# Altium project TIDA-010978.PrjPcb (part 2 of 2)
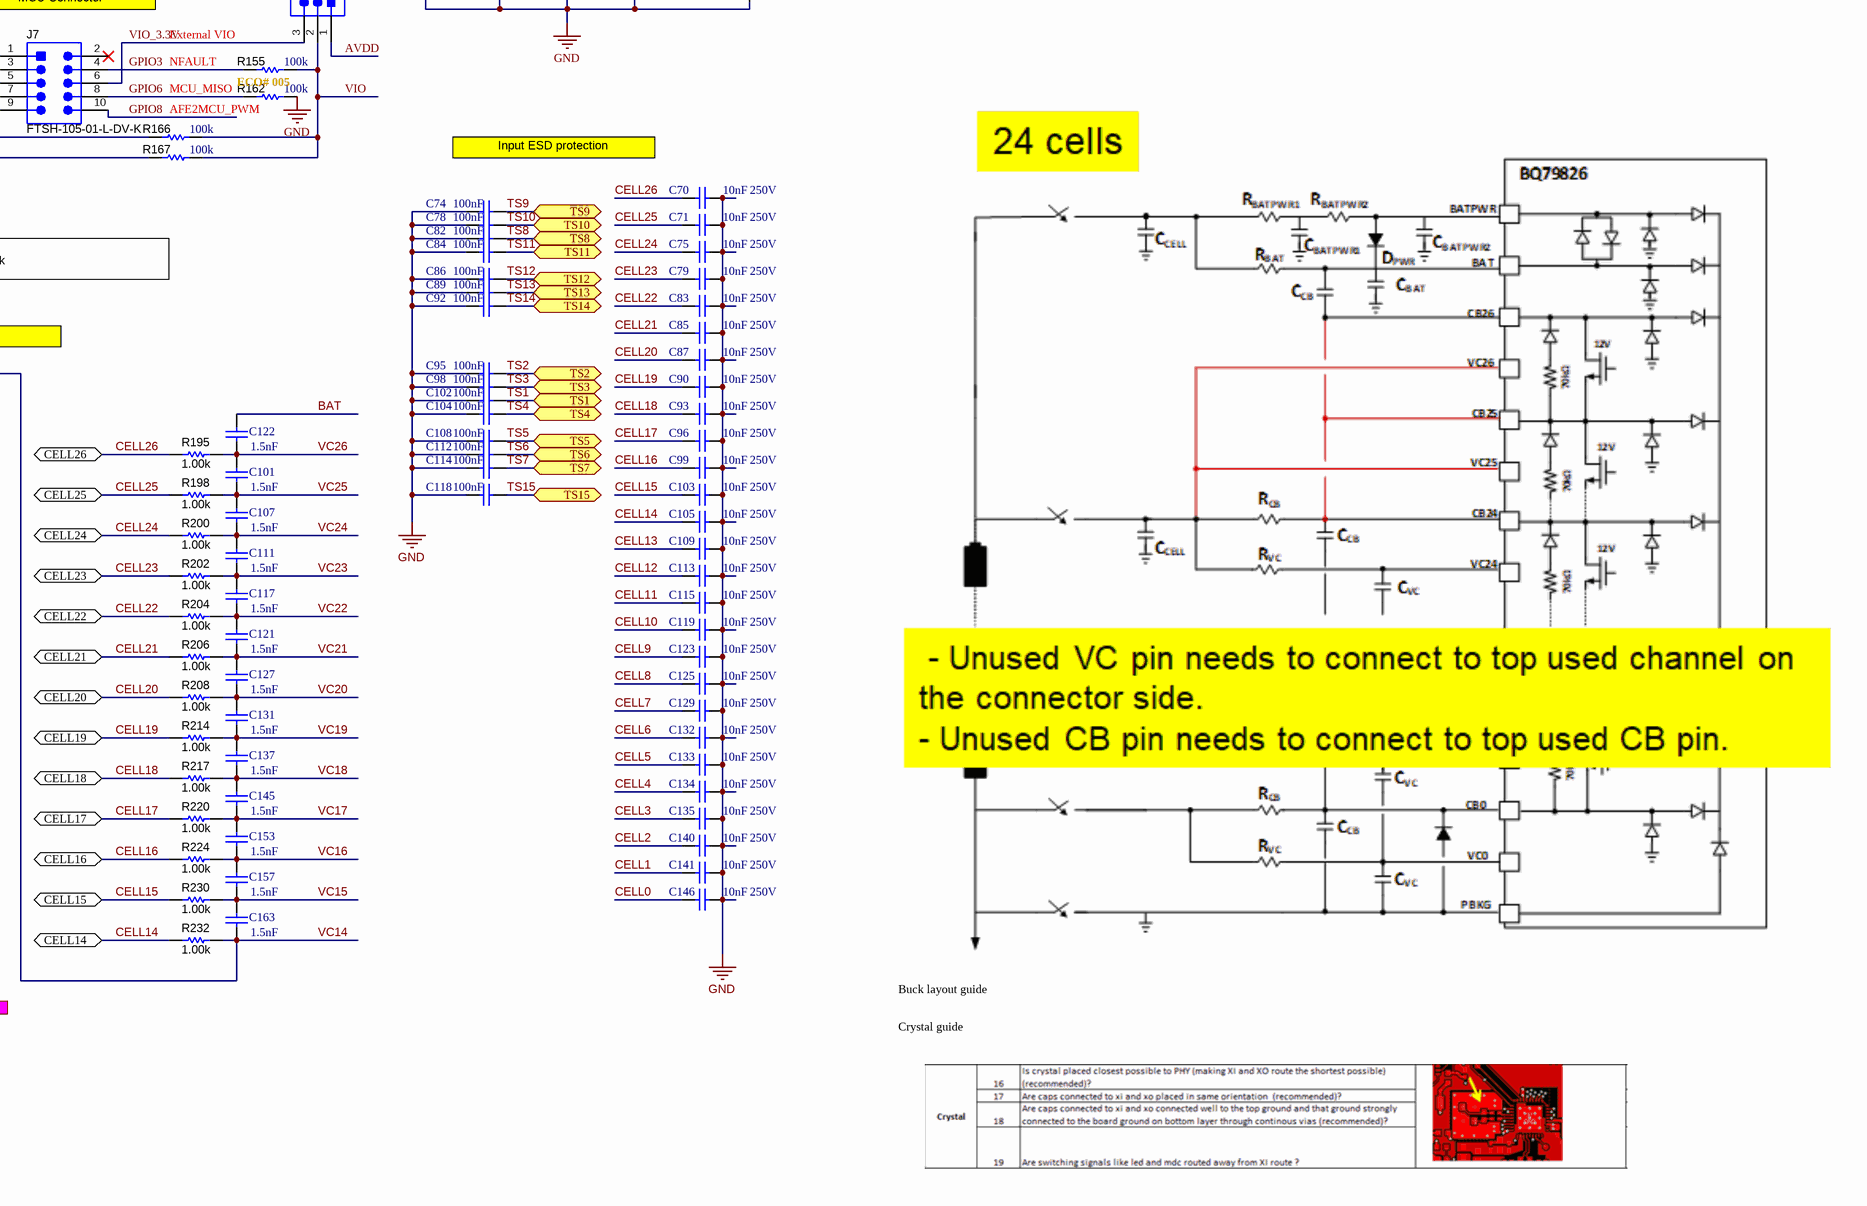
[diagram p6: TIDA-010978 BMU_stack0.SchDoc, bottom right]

## Sheet TIDA-010978 BMU_stack0.SchDoc (continued)

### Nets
GND: AVDD_LED1.1(K) C9.1 C10.2 C11.1 C16.1 C17.1 C18.2 C19.1 C20.1 C21.1 C22.1 C23.1 C24.1 C29.1 C30.1 C32.2 C33.2 C40.1 C51.2 C52.1 C58.1 C59.2 C60.2 C61.2 C62.2 C63.2 C64.2 C65.2 C66.2 C67.2 C68.2 C69.2 C70.1 C71.1 C72.2 C73.2 C74.1 C75.1 C76.2 C77.2 C78.1 C79.1 C80.2 C81.2 C82.1 C83.1 C84.1 C85.1 C86.1 C87.1 C88.2 C89.1 C90.1 C92.1 C93.1 C94.2 C95.1 C96.1 C98.1 C99.1 C102.1 C103.1 C104.1 C105.1 C108.1 C109.1 C112.1 C113.1 C114.1 C115.1 C118.1 C119.1 C123.1 C124.2 C125.1 C128.2 C129.1 C132.1 C133.1 C134.1 C135.1 C138.2 C139.2 C140.1 C141.1 C142.2 C143.1 C146.1 C147.2 C148.2 C149.1 C150.1 C151.1 C154.1 C155.1 C158.1 C159.2 C160.2 C161.1 C164.1 D1.2(A) D3.2(A) D4.2(GND) D5.3(GND) D6.3(GND) D7.2(ANODE) D8.2(GND) J1.1 J1.2 J4.5 J4.21 J4.30 J5.5 J5.21 J7.5 J9.1 J10.1 J12.6 LDOIN_LED1.1(K) NFAULT_LED1.1(K) Q1.1(Source_1) R76.1 R79.1 R141.2 R144.2 R147.2 R150.2 R153.1 R157.2 R160.2 R162.2 R164.2 R165.1 R177.2 R179.2 R181.2 R183.2 R185.1 R187.2 R189.2 R191.2 R236.1 RT1.2 TSREF_LED1.1(K) U1.65(REF_VSS) U1.89(AVSS) U1.91(VSS) U1.101(EP) U2.6(~{EN}) U2.8(GND) U3.6(~{EN}) U3.8(GND) U4.2(GND) U5.3(GND) Y2.2(GND) Y2.4(GND) ; port GND
AVDD: C21.2 C67.1 C88.1 J6.1 R128.1 U1.88(AVDD) U2.16(VDD) U3.16(VDD)
BAT: C9.2 C41.2 C122.2 D2.1(CATHODE) R1.1 U1.6(BAT)
BATPWR: C19.2 D2.2(ANODE) R7.2 U1.5(BATPWR)
BTSP: C31.2 U1.100(BTSP)
CB0: C53.1 C58.2 D4.1(IO) R122.2 R123.2 R124.2 R125.2 U1.62(CB0)
CB1: C46.1 C53.2 R100.2 R107.2 R112.2 R117.2 U1.60(CB1)
CB2: C42.1 C46.2 R80.2 R85.2 R90.2 R95.2 U1.58(CB2)
CB3: C34.1 C42.2 R58.2 R62.2 R66.2 R72.2 U1.56(CB3)
CB4: C25.1 C34.2 R38.2 R42.2 R46.2 R51.2 U1.54(CB4)
CB5: C12.1 C25.2 R21.2 R25.2 R29.2 R33.2 U1.52(CB5)
CB6: C12.2 C54.1 R2.2 R8.2 R12.2 R16.2 U1.50(CB6)
CB7: C47.1 C54.2 R101.2 R108.2 R113.2 R118.2 U1.48(CB7)
CB8: C43.1 C47.2 R81.2 R86.2 R91.2 R96.2 U1.46(CB8)
CB9: C35.1 C43.2 R59.2 R63.2 R67.2 R73.2 U1.44(CB9)
CB10: C26.1 C35.2 R39.2 R43.2 R47.2 R52.2 U1.42(CB10)
CB11: C13.1 C26.2 R22.2 R26.2 R30.2 R34.2 U1.40(CB11)
CB12: C13.2 C55.1 R3.2 R9.2 R13.2 R17.2 U1.38(CB12)
CB13: C48.1 C55.2 R102.2 R109.2 R114.2 R119.2 U1.36(CB13)
CB14: C44.1 C48.2 R82.2 R87.2 R92.2 R97.2 U1.34(CB14)
CB15: C36.1 C44.2 R60.2 R64.2 R68.2 R74.2 U1.32(CB15)
CB16: C27.1 C36.2 R40.2 R44.2 R48.2 R53.2 U1.30(CB16)
CB17: C14.1 C27.2 R23.2 R27.2 R31.2 R35.2 U1.28(CB17)
CB18: C14.2 C56.1 R4.2 R10.2 R14.2 R18.2 U1.23(CB18)
CB19: C49.1 C56.2 R103.2 R110.2 R115.2 R120.2 U1.21(CB19)
CB20: C45.1 C49.2 R83.2 R88.2 R93.2 R98.2 U1.19(CB20)
CB21: C37.1 C45.2 R61.2 R65.2 R69.2 R75.2 U1.17(CB21)
CB22: C28.1 C37.2 R41.2 R45.2 R49.2 R54.2 U1.15(CB22)
CB23: C15.1 C28.2 R24.2 R28.2 R32.2 R36.2 U1.13(CB23)
CB24: C15.2 C57.1 R5.2 R11.2 R15.2 R19.2 U1.11(CB24)
CB25: C50.1 C57.2 R104.2 R111.2 R116.2 R121.2 U1.9(CB25)
CB26: C41.1 C50.2 R84.2 R89.2 R94.2 R99.2 U1.7(CB26)
CELL0: C146.2 D7.1(CATHODE) J1.3 J4.10 R122.1 R123.1 R124.1 R125.1 R231.1 ; port CELL0
CELL1: C141.2 J1.4 J4.31 R100.1 R107.1 R112.1 R117.1 R229.1 ; port CELL1
CELL2: C140.2 J1.5 J4.11 R80.1 R85.1 R90.1 R95.1 R223.1 ; port CELL2
CELL3: C135.2 J1.6 J4.32 R58.1 R62.1 R66.1 R72.1 R219.1 ; port CELL3
CELL4: C134.2 J1.7 J4.12 R38.1 R42.1 R46.1 R51.1 R216.1 ; port CELL4
CELL5: C133.2 J1.8 J4.33 R21.1 R25.1 R29.1 R33.1 R213.1 ; port CELL5
CELL6: C132.2 J1.9 J4.13 R2.1 R8.1 R12.1 R16.1 R207.1 ; port CELL6
CELL7: C129.2 J1.10 J4.34 R101.1 R108.1 R113.1 R118.1 R205.1 ; port CELL7
CELL8: C125.2 J1.11 J4.14 R81.1 R86.1 R91.1 R96.1 R203.1 ; port CELL8
CELL9: C123.2 J1.12 J2.1 J4.35 R59.1 R63.1 R67.1 R73.1 R201.1 ; port CELL9
CELL10: C119.2 J2.2 J4.15 R39.1 R43.1 R47.1 R52.1 R199.1 ; port CELL10
CELL11: C115.2 J2.3 J4.36 R22.1 R26.1 R30.1 R34.1 R197.1 ; port CELL11
CELL12: C113.2 J2.4 J4.16 R3.1 R9.1 R13.1 R17.1 R194.1 ; port CELL12
CELL13: C109.2 J2.5 J4.37 R102.1 R109.1 R114.1 R119.1 R192.1 ; port CELL13
CELL14: C105.2 J2.6 J5.10 R82.1 R87.1 R92.1 R97.1 R232.1 ; port CELL14
CELL15: C103.2 J2.7 J5.31 R60.1 R64.1 R68.1 R74.1 R230.1 ; port CELL15
CELL16: C99.2 J2.8 J5.11 R40.1 R44.1 R48.1 R53.1 R224.1 ; port CELL16
CELL17: C96.2 J2.9 J5.32 R23.1 R27.1 R31.1 R35.1 R220.1 ; port CELL17
CELL18: C93.2 J2.10 J3.1 J5.12 R4.1 R10.1 R14.1 R18.1 R217.1 ; port CELL18
CELL19: C90.2 J3.2 J5.33 R103.1 R110.1 R115.1 R120.1 R214.1 ; port CELL19
CELL20: C87.2 J3.3 J5.13 R83.1 R88.1 R93.1 R98.1 R208.1 ; port CELL20
CELL21: C85.2 J3.4 J5.34 R61.1 R65.1 R69.1 R75.1 R206.1 ; port CELL21
CELL22: C83.2 J3.5 J5.14 R41.1 R45.1 R49.1 R54.1 R204.1 ; port CELL22
CELL23: C79.2 J3.6 J5.35 R24.1 R28.1 R32.1 R36.1 R202.1 ; port CELL23
CELL24: C75.2 J3.7 J5.15 R5.1 R11.1 R15.1 R19.1 R200.1 ; port CELL24
CELL25: C71.2 J3.8 J5.36 R104.1 R111.1 R116.1 R121.1 R198.1 ; port CELL25
CELL26: C70.2 J3.9 J5.16 R84.1 R89.1 R94.1 R99.1 R195.1 ; port CELL26
COMH_N: C151.2 R227.1 U1.95(COMHN)
COMH_P: C139.1 R211.1 U1.96(COMHP)
COML_N: C150.2 R226.2 U1.94(COMLN)
COML_P: C138.1 R209.2 U1.93(COMLP)
COMMH_N: D6.2(2_IO) J9.2 R227.2 R228.1
COMMH_N_OPT: C154.2 R222.1 R228.2 ; port COMMH_N_OPT
COMMH_P: D6.1(1_IO) J9.3 R211.2 R212.1
COMMH_P_OPT: C147.1 R212.2 R218.2 ; port COMMH_P_OPT
COMML_N: D5.2(2_IO) J10.2 R225.2 R226.1
COMML_N_OPT: C149.2 R221.1 R225.1 ; port COMML_N_OPT
COMML_P: D5.1(1_IO) J10.3 R209.1 R210.2
COMML_P_OPT: C148.1 R210.1 R215.2 ; port COMML_P_OPT
CRYSTAL_1.5V: C159.1 C161.2 R56.2 U4.5(OUT) U5.5(VCCO)
DVDD: C22.2 Q1.2(Gate_1) U1.90(DVDD)
GPIO1: C38.2 C52.2 R57.1 R105.2 U1.86(GPIO1)
GPIO2: C38.1 C51.1 R55.1 R78.1 U1.85(GPIO2)
GPIO2_R: J8.20 R78.2
GPIO3: J7.4 J8.17 Q1.5(Gate_2) R155.1 U1.84(GPIO3/~{FAULT}/INT1/RAVDD)
GPIO4: J7.3 J8.18 R165.2 U1.83(GPIO4/PSCLK)
GPIO5: J7.7 J8.15 R167.1 U1.82(GPIO5/PSDI/SMON)
GPIO6: C32.1 J7.8 J8.16 R37.2 R162.1
GPIO6_L: R37.1 U1.81(GPIO6/PSDO)
GPIO7: J7.9 J8.13 R166.1 U1.80(GPIO7/~{PCS}/INT2)
GPIO8: J7.10 J8.14 U1.79(GPIO8) U3.3(D)
GPIO9: J8.11 U1.78(GPIO9/INT3/I2C_SCL) U2.11(A0) U3.11(A0)
GPIO10: J8.12 U1.77(GPIO10/I2C_SDA) U2.10(A1) U3.10(A1)
GPIO11: J8.9 U1.76(GPIO11) U2.9(A2) U3.9(A2)
GPIO12: J8.10 U1.75(GPIO12) U2.3(D)
GPIO13: C94.1 J8.7 J12.2 R196.1 R236.2 U1.74(GPIO13/CSCLK)
GPIO14: J8.8 J12.3 R235.1 U1.73(GPIO14/CSDO)
GPIO15: J8.5 J12.4 R234.1 U1.72(GPIO15/CSDI/INT4)
GPIO16: J8.6 J12.5 R233.1 U1.71(GPIO16/~{CSS1})
GPIO17: J8.3 R71.2
GPIO17_OSC: C124.1 R71.1 U1.70(GPIO17/INT5) U5.4(Y) Y2.1(1_Crystal)
GPIO18: C155.2 J8.4 R56.1 R76.2 R77.2
GPIO18_OSC: C128.1 R77.1 U1.69(GPIO18) Y2.3(2_Crystal)
GPIO19: J8.1 U1.68(GPIO19)
GPIO20: J8.2 U1.67(GPIO20)
GPIO_R: J8.19 R105.1
LDOIN: C11.2 C16.2 C17.2 C18.1 L2.2 R126.2 R129.2 U1.92(LDOIN)
MCU_PWM: J7.1 U5.2(A)
MODE: R79.2 U1.97(MODE)
PWR: D1.1(K) J3.10 J5.17 R1.2 R6.1 ; port PWR
REF_P: C30.2 U1.64(REF_CAP)
SRN_IN: C39.2 C40.2 J11.1 R57.2
SRP_IN: C33.1 C39.1 J11.2 R55.2
SW: D3.1(K) L2.1 R20.2 R50.1 U1.99(SW)
TS1: C102.2 J4.1 R173.1 R180.2 R181.1 ; port TS1
TS1_MUX: C77.1 R180.1 U3.5(S5)
TS2: C95.2 J4.22 R175.1 R176.2 R177.1 ; port TS2
TS2_MUX: C81.1 R176.1 U3.4(S7)
TS3: C98.2 J4.2 R174.1 R178.2 R179.1 ; port TS3
TS3_MUX: C80.1 R178.1 U3.2(S6)
TS4: C104.2 J4.23 R172.1 R182.2 R183.1 ; port TS4
TS4_MUX: C76.1 R182.1 U3.1(S4)
TS5: C108.2 J4.3 R170.1 R186.2 R187.1 ; port TS5
TS5_MUX: C72.1 R186.1 U3.15(S2)
TS6: C112.2 J4.24 R169.1 R188.2 R189.1 ; port TS6
TS6_MUX: C69.1 R188.1 U3.14(S1)
TS7: C114.2 J4.4 R168.1 R190.2 R191.1 ; port TS7
TS7_MUX: C68.1 R190.1 U3.13(S0)
TS8: C82.2 J5.1 R136.1 R146.2 R147.1 ; port TS8
TS8_MUX: C64.1 R146.1 U2.5(S5)
TS9: C74.2 J5.22 R138.1 R140.2 R141.1 ; port TS9
TS9_MUX: C66.1 R140.1 U2.4(S7)
TS10: C78.2 J5.2 R137.1 R143.2 R144.1 ; port TS10
TS10_MUX: C65.1 R143.1 U2.2(S6)
TS11: C84.2 J5.23 R135.1 R149.2 R150.1 ; port TS11
TS11_MUX: C63.1 R149.1 U2.1(S4)
TS12: C86.2 J5.3 R133.1 R156.2 R157.1 ; port TS12
TS12_MUX: C61.1 R156.1 U2.15(S2)
TS13: C89.2 J5.24 R132.1 R159.2 R160.1 ; port TS13
TS13_MUX: C60.1 R159.1 U2.14(S1)
TS14: C92.2 J5.4 R131.1 R163.2 R164.1 ; port TS14
TS14_MUX: C59.1 R163.1 U2.13(S0)
TS15: C118.2 J5.25 R193.1 R196.2 RT1.1 ; port TS15
TS_R1: R171.1 R184.2 R185.2
TS_R1MUX: C73.1 R184.1 U3.12(S3)
TS_R2: R134.1 R152.2 R153.2
TS_R2MUX: C62.1 R152.1 U2.12(S3)
TSREF: C23.2 C24.2 R127.1 R131.2 R132.2 R133.2 R134.2 R135.2 R136.2 R137.2 R138.2 R168.2 R169.2 R170.2 R171.2 R172.2 R173.2 R174.2 R175.2 R193.2 U1.66(TSREF)
VC0: C162.1 C164.2 D8.1(IO) R231.2 U1.63(VC0)
VC1: C156.1 C162.2 R229.2 U1.61(VC1)
VC2: C152.1 C156.2 R223.2 U1.59(VC2)
VC3: C144.1 C152.2 R219.2 U1.57(VC3)
VC4: C136.1 C144.2 R216.2 U1.55(VC4)
VC5: C130.1 C136.2 R213.2 U1.53(VC5)
VC6: C126.1 C130.2 R207.2 U1.51(VC6)
VC7: C120.1 C126.2 R205.2 U1.49(VC7)
VC8: C116.1 C120.2 R203.2 U1.47(VC8)
VC9: C110.1 C116.2 R201.2 U1.45(VC9)
VC10: C106.1 C110.2 R199.2 U1.43(VC10)
VC11: C100.1 C106.2 R197.2 U1.41(VC11)
VC12: C97.1 C100.2 R194.2 U1.39(VC12)
VC13: C91.1 C97.2 R192.2 U1.37(VC13)
VC14: C91.2 C163.1 R232.2 U1.35(VC14)
VC15: C157.1 C163.2 R230.2 U1.33(VC15)
VC16: C153.1 C157.2 R224.2 U1.31(VC16)
VC17: C145.1 C153.2 R220.2 U1.29(VC17)
VC18: C137.1 C145.2 R217.2 U1.27(VC18)
VC19: C131.1 C137.2 R214.2 U1.22(VC19)
VC20: C127.1 C131.2 R208.2 U1.20(VC20)
VC21: C121.1 C127.2 R206.2 U1.18(VC21)
VC22: C117.1 C121.2 R204.2 U1.16(VC22)
VC23: C111.1 C117.2 R202.2 U1.14(VC23)
VC24: C107.1 C111.2 R200.2 U1.12(VC24)
VC25: C101.1 C107.2 R198.2 U1.10(VC25)
VC26: C101.2 C122.1 R195.2 U1.8(VC26)
VIO: C29.2 J6.2 J12.1 Q1.4(Source_2) R155.2 R166.2 R167.2 R233.2 R234.2 R235.2 U1.87(VIO)
VIO_3.3V: C158.2 C160.1 J6.3 J7.6 R70.2 U4.1(IN) U5.1(VCCI)
NetAVDD_LED1_2: AVDD_LED1.2(A) R128.2
NetC10_1: C10.1 R6.2 R7.1
NetC20_2: C20.2 R20.1
NetC31_1: C31.1 R50.2
NetC142_1: C142.1 R215.1 R221.2
NetC143_2: C143.2 R218.1 R222.2
NetDVDD_LED1_1: DVDD_LED1.1(K) Q1.6(Drain_1)
NetDVDD_LED1_2: DVDD_LED1.2(A) R126.1
NetLDOIN_LED1_2: LDOIN_LED1.2(A) R129.1
NetNFAULT_LED1_2: NFAULT_LED1.2(A) R130.1
NetQ1_3: Q1.3(Drain_2) R130.2
NetR70_1: R70.1 U4.3(EN)
NetR127_2: R127.2 TSREF_LED1.2(A)

Not connected (* = marked no-connect by the designer): J4 6* 7* 8* 9* 17* 18* 19* 20* 25* 26* 27* 28* 29* 38* 39* 40* 41(MNT_1)* 42(MNT_2)*; J5 6* 7* 8* 9* 18* 19* 20* 26* 27* 28* 29* 30* 37* 38* 39* 40* 41(MNT_1)* 42(MNT_2)*; J7 2*; U1 1(NC)* 2(NC)* 3(NC)* 4(NC)* 24(NC)* 25(NC)* 26(NC)* 98(NC)*; U2 7(NC)*; U3 7(NC)*; U4 4(NC)*

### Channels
A1: designators end in _A1; ports CELL0=CELL0_A1 CELL1=CELL1_A1 CELL2=CELL2_A1 CELL3=CELL3_A1 CELL4=CELL4_A1 CELL5=CELL5_A1 CELL6=CELL6_A1 CELL7=CELL7_A1 CELL8=CELL8_A1 CELL9=CELL9_A1 CELL10=CELL10_A1 CELL11=CELL11_A1 CELL12=CELL12_A1 CELL13=CELL13_A1 CELL14=CELL14_A1 CELL15=CELL15_A1 CELL16=CELL16_A1 CELL17=CELL17_A1 CELL18=CELL18_A1 CELL19=CELL19_A1 CELL20=CELL20_A1 CELL21=CELL21_A1 CELL22=CELL22_A1 CELL23=CELL23_A1 CELL24=CELL24_A1 CELL25=CELL25_A1 CELL26=CELL26_A1 COMMH_N_OPT=COMMH_N_OPT COMMH_P_OPT=COMMH_P_OPT COMML_N_OPT=COMML_N_OPT COMML_P_OPT=COMML_P_OPT GND=GND PWR=PWR_A1 TS1=TS1_A1 TS2=TS2_A1 TS3=TS3_A1 TS4=TS4_A1 TS5=TS5_A1 TS6=TS6_A1 TS7=TS7_A1 TS8=TS8_A1 TS9=TS9_A1 TS10=TS10_A1 TS11=TS11_A1 TS12=TS12_A1 TS13=TS13_A1 TS14=TS14_A1 TS15=TS15_A1
A2: designators end in _A2; ports CELL0=CELL0_A2 CELL1=CELL1_A2 CELL2=CELL2_A2 CELL3=CELL3_A2 CELL4=CELL4_A2 CELL5=CELL5_A2 CELL6=CELL6_A2 CELL7=CELL7_A2 CELL8=CELL8_A2 CELL9=CELL9_A2 CELL10=CELL10_A2 CELL11=CELL11_A2 CELL12=CELL12_A2 CELL13=CELL13_A2 CELL14=CELL14_A2 CELL15=CELL15_A2 CELL16=CELL16_A2 CELL17=CELL17_A2 CELL18=CELL18_A2 CELL19=CELL19_A2 CELL20=CELL20_A2 CELL21=CELL21_A2 CELL22=CELL22_A2 CELL23=CELL23_A2 CELL24=CELL24_A2 CELL25=CELL25_A2 CELL26=CELL26_A2 COMMH_N_OPT=COMMH_N_OPT COMMH_P_OPT=COMMH_P_OPT COMML_N_OPT=COMML_N_OPT COMML_P_OPT=COMML_P_OPT GND=GND PWR=PWR_A2 TS1=TS1_A2 TS2=TS2_A2 TS3=TS3_A2 TS4=TS4_A2 TS5=TS5_A2 TS6=TS6_A2 TS7=TS7_A2 TS8=TS8_A2 TS9=TS9_A2 TS10=TS10_A2 TS11=TS11_A2 TS12=TS12_A2 TS13=TS13_A2 TS14=TS14_A2 TS15=TS15_A2

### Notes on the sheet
- (near R1) ECO# 004
- HPCR0805J68R0KT for 100mA
  HPCR0805J39R0KT for 187mA prefer
- 100mA CB current
- (near R6) ECO# 002
- (near R7) ECO# 003
- ESR = 2.4mOhm @ 300kHz
- DC Derating -> 7uF @ 6V
- ECO# 012
- EIS_SRN
- Cell balancing
- EIS_SRP
- (near R37) MCU_MOSI
- (near R37) MCU_SCLK
- (near R37) NFAULT
- (near U1) ECO# 013
- (near R37) EIS_PWM
- (near R37) MCU_NCS
- (near R37) I2C_SCL
- I2C_SDA
- EIS_FAN_EN
- MCU_MISO
- (near C51) ECO# 014
- MSPI_MOSI
- MSPI_MISO
- MSPI_SCLK
- EIS_NTC_IN
- ECO# 007
- If AVDD on, the 826 will work in SPI communication and be a base device.
- (near U1) If AVDD off, the 826 will work in Daisy Chain communication and be a stack/group device.
- (near R71) MSPI_NCS
- (near R77) NTC2
- (near R77) NTC3
- ECO# 014
- ECO# 015
- To ACB SPI
- (near Y2) ECO# 006
- (near U4) ECO# 011
- (near J12) VIO
- (near J1) To ACB
- (near J12) GND
- (near J12) MSPI_MOSI
- (near J12) MSPI_MISO
- (near J12) MSPI_SCLK
- (near J12) MSPI_NCS
- (near U5) ECO# 011
- (near D4) ECO# 001
- 61301011121
- Cell temperature
- SPI Break-Out
- Target: Show 26 cells Thermistors
  1.  Base device(10 used GPIOs).
  If SPI is used, GPIO3~7  will be used. So GPIO3~7 will not show as a case.
  If external OSC is used, GPIO 17 and 18 will be used.
  GPIO 1,2 is used for EIS current measurement. So if other 12 pins to cover 26 thermistors, which will need 3 TMUX(21s)+(12-6)pins
  2. Not base device(20 used GPIOs) with 2MUX for 29 thermistors
  Here is an example of 2 TMUX for 14 thermistors (GPIO8m/12m/9~
  1 control,TS1~TS14 all has resistors  SMTed as example)+ TS15 to GPIO13. 14s GPIO(GPIO1~7, GPIO14~|0)  is reserved.
  3. Not base device(20 used GPIOs) with 1MUX for 23 thermistors(4GPIOs for 7 thermistors+16 reserved)
- (near Q1) NFAULT
- (near J7) MCU Connector
- (near R155) External VIO
- (near R165) MCU2AFE_PWM
- (near R165) MCU_SCLK
- (near R165) MCU_MOSI
- (near R165) MCU_NCS
- NFAULT
- AFE2MCU_PWM
- ECO# 005
- Input ESD protection
- As a stack, no OSC required
  As a base, MCU provide reference clock
- (near C91) ECO# 005
- (near C91) Cell voltage VC
- (near R196) example of thermistor input
- Communication
- board use transformer ISO
  IF use CAP ISO need change Rterminal to 150Ω
- <---- TO WORLD
- (near R209) <---- DEVICE SIDE
- DEVICE SIDE ----->
- TO WORLD ----->
- ECO# 010
- (near R225) Component Values Change based ISO type.
- (near R225) Please check BQ798xx-Q1 Datasheet.
- (near R228) Component Values Change based ISO type.
- (near R228) Please check BQ798xx-Q1 Datasheet.
- (near R222) ECO# 014
- (near D8) ECO# 009
- Buck layout guide
  https://www.ti.com/lit/an/snva721a/snva721a.pdf?ts=1754037240159&ref_url=https%253A%252F%252Fwww.ti.com%252Fsitesearch%252Fen-us%252Fdocs%252Funiversalsearch.tsp%253FlangPref%253Den-US%2526searchTerm%253DSW+layout%2526nr%253D13509
- Crystal guide
  https://www.ti.com/lit/an/slaa322d/slaa322d.pdf?ts=1754044588718&ref_url=https%253A%252F%252Fwww.ti.com%252Fsitesearch%252Fen-us%252Fdocs%252Funiversalsearch.tsp%253FlangPref%253Den-US%2526nr%253D5857%2526searchTerm%253DCrystal+layout

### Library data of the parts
AVDD_LED1 DVDD_LED1 LDOIN_LED1 TSREF_LED1 = CMP-0002905-2: LED, Green, SMD; Manufacturer: Wurth Elektronik; Value1: W; Value2: 3.2V; Io_A: 20mA; Angle: 140; Tjmax_C: 85°C
C9 = CMP-0006852-4: CAP, CERM, 0.01 uF, 200 V, +/- 10%, X7R, 0603; Manufacturer: Kemet; TaMin_C: -55°C; Polarized: N; SizeAreaWB_mm2: 4.68; Value1: Unknown; U/M: EA; Value: 0.01uF; TaMax_C: 125°C; SizeZ_mm: 1; SizeX_mm: 1.6; SizeY_mm: 0.8; SizeArea_mm2: 1.28; AEC Category: Q200
C10 = CMP-0085301-1: CAP, CERM, 1 µF, 250 V,+/- 10%, X7R, AEC-Q200 Grade 1, 2220; Manufacturer: TDK; AEC Qualified: Y; TaMax_C: 125°C; U/M: EA; SizeZ_mm: 2.8; Value: 1uF; Cap_Case: 2220; TaMin_C: -55°C; AEC Category: Q200; SizeArea_mm2: 28.5; SizeY_mm: 5; AEC Grade: 1; SizeAreaWB_mm2: 53.9; SizeX_mm: 5.7; Polarized: N
C11 C22 C30 = CMP-0097608-1: 0.47 µF ±10% 16V Ceramic Capacitor X7R 0603 (1608 Metric); Manufacturer: Wurth Electronics; AEC Qualified: No; Value: 470nF; TempCo: 15%; SizeZ_mm: 0.87mm
C12-C15 C25-C28 C34-C37 C41-C50 C53-C58 C158 C159 = CMP-0094775-1: Chip Multilayer Ceramic Capacitors for General Purpose, 0402, 1.0uF, X6S, 22%, 10%, 16V; Manufacturer: Murata; Value: 1µF; AEC Qualified: No; SizeZ_mm: 0.6mm
C16 C17 = CMP-03913-65419739-1: 885012107014 Ceramic Capacitor, Multilayer, Ceramic, 16V, 20% +Tol, 20% -Tol, X5R, 15% TC, 10uF, Surface Mount, 0805; Manufacturer: Wurth Elektronik; Insulation Resistance: 10MΩ
C18 = CMP-0007965-2: CAP, CERM, 10 uF, 16 V, +/- 10%, X7S, AEC-Q200 Grade 1, 0805; Manufacturer: TDK; PartNumber: CGA4J1X7S1C106K125AC; TaMin_C: -55°C; Polarized: N; SizeAreaWB_mm2: 6.75; Value1: Unknown; U/M: EA; Value: 10uF; TaMax_C: 125°C; SizeZ_mm: 1.45; SizeX_mm: 2; SizeY_mm: 1.25; Cap_Case: 0805; Value2: 16V; SizeArea_mm2: 2.5; AEC Qualified: Y; Cap_F: 10µF; AEC Grade: 1; AEC Category: Q200
C19 = CMP-03020-023125-1: C1206 0.15 μF X7R 10.00% 250 V; Manufacturer: KEMET; Material: Ceramic; Temperature Coefficient: 15%; Tolerance: 0.1; Value: 0.15 μF; Automotive Grade: Grade 0; Voltage Rating: 250 V
C20 = CMP-0115820-1: WCAP-CSMH Multilayer Ceramic Chip Capacitor, Mid and High Voltage, size 0603, NP0 Class I, 220pF, 250VDC; Manufacturer: Wurth Elektronik; Manufacturer Part Number: 885342006004; Capacitance Tolerance: 5%; Case/Size Code: 0603; Insulation Resistance: 10GOhm; Q Factor: 1000; Rated Voltage (DC): 250V; Technical Reference: NP00603221J250DFCT10000
C21 C23 = CMP-0006833-4: CAP, CERM, 1 uF, 25 V, +/- 10%, X7R, 0603; Manufacturer: Wurth Elektronik; TaMin_C: -55°C; Polarized: N; SizeAreaWB_mm2: 4.68; Value1: Unknown; U/M: EA; Value: 1uF; TaMax_C: 125°C; SizeZ_mm: 1; SizeX_mm: 1.6; SizeY_mm: 0.8; SizeArea_mm2: 1.28; AEC Category: Q200
C24 = CMP-0119395-1: WCAP-CSGP Multilayer Ceramic Chip Capacitor, General Purpose, size 0603, X7R, 10nF, 50VDC; Manufacturer: Wurth Elektronik; Capacitance Tolerance: +/-10%; Case/Size Code: 0603; Dissipation Factor: 2.5%; Insulation Resistance: 10GOhm; Technical Reference: X7R0603103K050DFCT10000
C29 C33 C40 C51 C52 C155 = CMP-03913-130590226-1: 885012205092 Cap, 0.1Uf, 50V, Mlcc, 0402 Rohs Compliant: Yes; Manufacturer: Wurth Elektronik; Insulation Resistance: 500MΩ
C31 = CMP-0119297-1: WCAP-CSGP Multilayer Ceramic Chip Capacitor, General Purpose, size 0402, X7R, 10nF, 50VDC; Manufacturer: Wurth Elektronik; Capacitance Tolerance: +/-10%; Case/Size Code: 0402; Dissipation Factor: 2.5%; Insulation Resistance: 10GOhm; Rated Voltage (DC): 50V; Technical Reference: X7R0402103K050DFCT10000
C32 = CMP-0006467-2: CAP, CERM, 47 pF, 50 V, +/- 1%, C0G/NP0, 0402; Manufacturer: MuRata; PartNumber: GRM1555C1H470FA01D; TaMin_C: -55°C; Polarized: N; SizeAreaWB_mm2: 3; Value1: Unknown; U/M: EA; Value: 47pF; TaMax_C: 125°C; SizeZ_mm: 0.6; SizeX_mm: 1; SizeY_mm: 0.5; Value2: 50V; AEC Category: Q200
C38 = CMP-0119376-1: WCAP-CSGP Multilayer Ceramic Chip Capacitor, General Purpose, size 0603, X7R, 150nF, 25VDC; Manufacturer: Wurth Elektronik; Capacitance Tolerance: +/-10%; Dissipation Factor: 3.5%; Insulation Resistance: 3.3GOhm; Rated Voltage (DC): 25V; Technical Reference: X7R0603154K025DFCT10000
C39 = CMP-0007136-5: CAP, CERM, 1 uF, 16 V, +/- 10%, X7R, AEC-Q200 Grade 1, 0603; Manufacturer: MuRata; PartNumber: GCM188R71C105KA64D; TaMin_C: -55°C; Polarized: N; SizeAreaWB_mm2: 4.68; Value1: Unknown; U/M: EA; Value: 1uF; TaMax_C: 125°C; SizeZ_mm: 1; SizeX_mm: 1.6; SizeY_mm: 0.8; Value2: 16V; SizeArea_mm2: 1.28; CompType: Capacitor; AEC Qualified: Y; Cap_F: 1µF; AEC Category: Q200
C59-C66 C68 C69 C72 C73 C76 C77 C80 C81 = CMP-0119302-1: WCAP-CSGP Multilayer Ceramic Chip Capacitor, General Purpose, size 0402, X7R, 100nF, 50VDC; Manufacturer: Wurth Elektronik; Capacitance Tolerance: +/-10%; Case/Size Code: 0402; Dissipation Factor: 10%; Insulation Resistance: 0.5GOhm; Rated Voltage (DC): 50V; Technical Reference: X7R0402104K050DFCT10000
C67 C88 C94 C142 C143 C160 C161 = CMP-0006356-2: CAP, CERM, 0.1 uF, 50 V, +/- 10%, X7R, AEC-Q200 Grade 1, 0402; Manufacturer: MuRata; TaMin_C: -55°C; Polarized: N; SizeAreaWB_mm2: 3; Value1: Unknown; U/M: EA; Value: 0.1uF; TaMax_C: 125°C; SizeZ_mm: 0.6; SizeX_mm: 1; SizeY_mm: 0.5; Value2: 50V; AEC Qualified: Y; Cap_F: 100nF; AEC Category: Q200
C70 C71 C75 C79 C83 C85 C87 C90 C93 C96 C99 C103 C105 C109 C113 C115 C119 C123 C125 C129 C132-C135 C140 C141 C146 = CMP-0119785-1: WCAP-CSMH Multilayer Ceramic Chip Capacitor, Mid and High Voltage, size 0603, X7R Class II, 10nF, 250VDC; Manufacturer: Wurth Elektronik; Capacitance Tolerance: 10%; Case/Size Code: 0603; Dissipation Factor: 2.5%; Insulation Resistance: 10GOhm; Technical Reference: X7R0603103K250DFCT10000
C74 C78 C82 C84 C86 C89 C92 C95 C98 C102 C104 C108 C112 C114 C118 = CMP-0119301-1: WCAP-CSGP Multilayer Ceramic Chip Capacitor, General Purpose, size 0402, X7R, 100nF, 25VDC; Manufacturer: Wurth Elektronik; Capacitance Tolerance: +/-10%; Case/Size Code: 0402; Dissipation Factor: 10%; Insulation Resistance: 5GOhm; Rated Voltage (DC): 25V; Technical Reference: X7R0402104K025DFCT20000
C91 C97 C100 C101 C106 C107 C110 C111 C116 C117 C120-C122 C126 C127 C130 C131 C136 C137 C144 C145 C152 C153 C156 C157 C162-C164 = CMP-0119292-1: WCAP-CSGP Multilayer Ceramic Chip Capacitor, General Purpose, size 0402, X7R, 1.5nF, 50VDC; Manufacturer: Wurth Elektronik; Capacitance Tolerance: +/-10%; Case/Size Code: 0402; Dissipation Factor: 2.5%; Insulation Resistance: 10GOhm; Rated Voltage (DC): 50V; Technical Reference: X7R0402152K050DFCT10000
C124 C128 = CMP-0118817-1: WCAP-CSGP Multilayer Ceramic Chip Capacitor, General Purpose, size 0402, NP0, 22pF, 50VDC; Manufacturer: Wurth Elektronik; Capacitance Tolerance: +/-5%; Case/Size Code: 0402; Insulation Resistance: 10GOhm; Q Factor: 840; Rated Voltage (DC): 50V; Technical Reference: NP00402220J050DFCT10000
C138 C139 C147-C151 C154 = CMP-0118819-1: WCAP-CSGP Multilayer Ceramic Chip Capacitor, General Purpose, size 0402, NP0, 47pF, 50VDC; Manufacturer: Wurth Elektronik; Capacitance Tolerance: +/-5%; Insulation Resistance: 10GOhm; Q Factor: 1000; Rated Voltage (DC): 50V; Technical Reference: NP00402470J050DFCT10000
D1 = CMP-0084980-1: Diode, TVS, Uni, 120 V, 193 Vc, 400 W, 2.1 A, SMA; Manufacturer: Littelfuse; Value: 120V; SizeX_mm: 5.59; Vc: 193V; Ipp: 2.1A; Vbr_Max: 147V; AEC Qualified: N; Vbr_Min: 133V; SizeY_mm: 2.92; Ppk: 400W; SizeZ_mm: 2.87; AEC Category: Q101; SizeAreaWB_mm2: 37.3428; RJA_CperW: 120; SizeArea_mm2: 16.3228
D2 = CMP-0123893-1: 11.5V Clamp 87A (8/20µs) Ipp Tvs Diode Surface Mount DO-219AD (MicroSMP); Manufacturer: Vishay; AEC Qualified: Yes; SizeZ_mm: 0.73mm; VRWM: 3.3V; Ppk: 150W; AEC Grade: Grade 0; Breakdown Voltage: 4.1V; Direction: Unidirectional; Number Of Channels: 1; Standoff Height: 0mm; TJmax_C: +150°C
D3 = CMP-0086794-2: DIODE SCHOTTKY 200V POWERDI123; Manufacturer: Diodes; Symbol Name: SYM-DFLS1200Q-7; AEC Qualified: Yes; SizeZ_mm: 1mm; TJmax_C: 150°C; AEC Category: Q101
D4 D8 = CMP-0126010-1: 7.7V (Typ) Clamp 25A (8/20µs) Ipp Tvs Diode Surface Mount SOD-323; Manufacturer: Texas Instruments; AEC Qualified: No; SizeZ_mm: 1mm; VRWM: 3.6V; Ppk: 170W; Cap_F: 4.5pF; Direction: Unidirectional; Number Of Channels: 1; Standoff Height: 0mm; TaMax_C: +150°C; TaMin_C: -55°C
D5 D6 = CMP-0120072-1: 2-Channel ESD Protection Diode; Manufacturer: Texas Instruments; SizeZ_mm: 1.12mm; Direction: Bidirectional; Number Of Channels: 2; Standoff Height: 0.01mm
D7 = CMP-0033054-1: SMD16PL Series 60 V 1 A Surface Mount Schottky Rectifier - SOD-123FL; Manufacturer: Micro Commercial Co; AEC Qualified: No; SizeZ_mm: 1.35mm; TJmax_C: 125°C; Vf_V: 60V; Cap_F: 40pF; Forward Current: 1A; Max Surge Forward Current: 30A; Peak Reverse Current: 0.1mA
J1 = CMP-1502-01086-4: THT Vertical Pin Header WR-PHD, Pitch 2.54 mm, Single Row, 12 pins; Manufacturer: Wurth Elektronik; Connector Type: Male Pin; Current Rating: 3A; Gender: Male; Contact Resistance: 20mΩ; Operating Supply Voltage: 250V; Number of Positions: 12; Pitch: 2.54mm
J2 J3 = CMP-0054804-1: Header, 2.54mm, 10x1, Gold, TH; Manufacturer: Wurth Elektronik; CNHeader: TRUE; Shrouded: N; Gender: Male; Row_Count: 1; Pitch_mm: 2.54; CT: FALSE
J4 = CMP-0123118-1: 2.00mm Wafer, Right Angle Connector, 40pins, Key-A With CPA Feature; Manufacturer: BEIJIDA ELECTRONICS TECHNOLOGY; ContactFinish: Tin,Nickel; Current_A: 3A; Row_Count: 2; Voltage_V: 60V; AEC Qualified: No; Conn Gender: Male; DUT-Pitch_mm: 2mm; SizeZ_mm: 9.6mm
J5 = CMP-0123118-1: 2.00mm Wafer, Right Angle Connector, 40pins, Key-A With CPA Feature; Manufacturer: BEIJIDA ELECTRONICS TECHNOLOGY; PartNumber: 141114-214010; ContactFinish: Tin,Nickel; Current_A: 3A; Row_Count: 2; Voltage_V: 60V; AEC Qualified: No; Conn Gender: Male; DUT-Pitch_mm: 2mm; SizeZ_mm: 9.6mm
J6 J9 J10 = CMP-0002338-1: Header, 100mil, 3x1, Tin, TH; Manufacturer: Sullins Connector Solutions; CNHeader: TRUE; Current_A: 3A; Green_Lifecycle: Not Set; Shrouded: N; Gender: Male; Green_REACh: Incomplete; Voltage_V: 1.8kV; Row_Count: 1; Pitch_mm: 2.54; CT: FALSE; Cert_UL: Y
J7 = CMP-0075634-2: Header(Shrouded), 1.27mm, 5x2, Gold, SMT; Manufacturer: Samtec; Pitch_mm: 1.27; Gender: Male; Cert_CSA: Y; Current_A: 3.3A; Row_Count: 2
J8 = CMP-0054591-2: Header, 2.54mm, 10x2, Gold, TH; Manufacturer: Sullins Connector Solutions; Shrouded: N; Gender: Male; Row_Count: 2; RowSpacing_mm: 2.54
J11 = CMP-0080461-1: Header(shrouded), 2mm, 2x1, Tin, TH; Manufacturer: JST Manufacturing; Pitch_mm: 2; Gender: Male; Cert_CSA: Y; Voltage_V: 100V; Current_A: 2A; Row_Count: 1
J12 = CMP-0097616-1: Conn Unshrouded Header HDR 6 POS 1.27mm Solder ST SMD Automotive T/R; Part Number: FTSH-103-01-F-DV-TR; Obsolete Part: false; Manufacturer: Samtec; Current_A: 3.4A; Row_Count: 2; Is Female: no; Conn Orientation: Vertical; SizeZ_mm: 6.23mm; ContactFinish: Gold,Nickel; Conn Gender: Male; Standoff Height: 0.15mm
L2 = CMP-03913-61645204-1: 74404042101 WE-LQS SMD Power Inductor 100uH; Manufacturer: Wurth Elektronik; Tolerance: 20%; Shielding: Shielded; Test Frequency: 100kHz; Self Resonant Frequency: 8MHz; DC Resistance (DCR): 1.43Ω; Saturation Current: 560mA
NFAULT_LED1 = CMP-0002947-3: LED, Red, SMD; Manufacturer: Wurth Elektronik; Value1: 0.072W; Vf_V: 2V; Angle: 140; Tjmax_C: 85°C; Vr_V: 5V; Io_A: 30mA; Power_TotalModule: 72mW
Q1 = CMP-0098136-1: Trans MOSFET N/P-CH Si 20V 0.8A 6-Pin ES T/R; Manufacturer: Toshiba Semiconductor and Storage; Transconductance: 1.4/1S; Threshold Vgs Min: 0.4/-0.3V; Threshold Vgs Max: 1V; Power_W: 150mW; ChMode: False; Number Of Channels: 2; Pulse Drain Current: 1600mA; AEC Qualified: No; Number Of N Channels: 1; Turn Off Delay Time: 8.5/26ns; Vgs_V: 8V; IdsMax_A: 800mA; VdsMax_V: 1.2V; TJmax_C: +150°C; Turn On Delay Time: 5.5/8ns; Typ Forward Diode Voltage: -0.82/0.9V; SizeZ_mm: 0.6mm
R1 = CMP-0021100-3: RES, 28.0, 1%, 0.125 W, AEC-Q200 Grade 0, 0805; Manufacturer: Vishay-Dale; Power_W: 125mW; TempCo: 100 ppm/C; Value_Code: 28R0; Value: 28.0; EIA_Code: E96; Res_ohm: 28; SizeX_mm: 2; SizeY_mm: 1.25; SizeZ_mm: 1.45; SizeArea_mm2: 2.5; AEC Qualified: Y; VDC_V: 150V; AEC Category: Q200; AEC Grade: 0
R2-R5 R8-R19 R21-R36 R38-R49 R51-R54 R58-R69 R72-R75 R80-R104 R107-R125 = CMP-0020585-3: RES, 68, 5%, 0.125 W, AEC-Q200 Grade 0, 0805; Manufacturer: RESI; Power_W: 125mW; TempCo: 200 ppm/C; Value_Code: 68R0; Value: 68; EIA_Code: E24; SizeX_mm: 2; SizeY_mm: 1.25; SizeZ_mm: 1.45; Value2: 0.125W; SizeArea_mm2: 2.5; AEC Qualified: Y; VDC_V: 150V; AEC Category: Q200; AEC Grade: 0
R6 = CMP-0127321-1: RES Thick Film, 62Ω, 5%, 0.75W, 200ppm/°C, 1206; Manufacturer: Vishay Dale; AEC Grade: Grade 0; AEC Qualified: Yes; SizeZ_mm: 0.65mm; VDC_V: 200V; Value: 62
R7 = CMP-0020567-3: RES, 51, 5%, 0.125 W, AEC-Q200 Grade 0, 0805; Manufacturer: Vishay-Dale; Power_W: 125mW; TempCo: 200 ppm/C; Value_Code: 51R0; Value: 51; EIA_Code: E24; SizeX_mm: 2; SizeY_mm: 1.25; SizeZ_mm: 1.45; SizeArea_mm2: 2.5; AEC Qualified: Y; VDC_V: 150V; AEC Category: Q200; AEC Grade: 0
R20 = CMP-0025703-4: RES, 10, 5%, 0.1 W, AEC-Q200 Grade 0, 0603; Manufacturer: Vishay-Dale; PartNumber: CRCW060310R0JNEA; Power_W: 100mW; TempCo: 200 ppm/C; Value_Code: 10R0; Value: 10; EIA_Code: E24; SizeX_mm: 1.6; SizeY_mm: 0.8; SizeZ_mm: 1; Value2: 0.1W; SizeArea_mm2: 1.28; AEC Qualified: Y; VDC_V: 75V; AEC Category: Q200; AEC Grade: 0
R37 = CMP-0022769-5: RES, 120, 1%, 0.1 W, 0603; Manufacturer: Yageo; Power_W: 100mW; TempCo: 100 ppm/C; Value_Code: 120R; Value: 120; SizeX_mm: 1.6; SizeY_mm: 0.8; SizeZ_mm: 1; Value2: 0.1W; SizeArea_mm2: 1.28; AEC Qualified: N; VDC_V: 75V; AEC Category: Q200; SizeAreaWB_mm2: 4.68
R50 = CMP-0025874-4: RES, 0, 5%, 0.1 W, AEC-Q200 Grade 0, 0603; Manufacturer: Panasonic; Power_W: 100mW; TempCo: 600 ppm/C; Value_Code: 0000; Value: 0; EIA_Code: E24; SizeX_mm: 1.6; SizeY_mm: 0.8; SizeZ_mm: 1; Value2: 0.1W; SizeArea_mm2: 1.28; AEC Qualified: Y; VDC_V: 50V; AEC Category: Q200; SizeAreaWB_mm2: 4.68
R55 R57 = CMP-0088611-1: Res Thick Film 0402 10 Ohm 1% 0.1W(1/10W) ±100ppm/C Molded SMD Automotive Punched T/R; Manufacturer: Panasonic; VDC_V: 50V; TempCo: 100ppm/°C; Power_W: 100mW; AEC Qualified: Yes; AEC Grade: Grade 0; SizeZ_mm: 0.4mm
R56 R76 = CMP-0025959-3: RES, 10.2 k, 1%, 0.063 W, AEC-Q200 Grade 0, 0402; Manufacturer: Vishay-Dale; Power_W: 63mW; TempCo: 100 ppm/C; Value_Code: 10k2; Value: 10.2k; EIA_Code: E96; SizeX_mm: 1; SizeY_mm: 0.5; SizeZ_mm: 0.6; Value2: 0.063W; AEC Qualified: Y; VDC_V: 50V; AEC Category: Q200; AEC Grade: 0
R70 R71 R77-R79 R105 R209 R211 R226 R227 = CMP-0026992-3: RES, 0, 5%, 0.1 W, AEC-Q200 Grade 0, 0402; Manufacturer: Panasonic; VDC_V: 50V; Power_W: 100mW; Value: 0; Value_Code: 0000; Value2: 0.1W; EIA_Code: E24; TempCo: 600 ppm/C; AEC Category: Q200; AEC Qualified: Y; SizeX_mm: 1; SizeY_mm: 0.5; SizeZ_mm: 0.6; SizeAreaWB_mm2: 3
R126 R129 R153 R185 = CMP-0026739-1: RES, 4.70 k, 1%, 0.0625 W, 0402; Manufacturer: Yageo America; Power_W: 62.5mW; TempCo: 100 ppm/C; Value_Code: 4k70; U/M: EA; Value: 4.70k; Res_ohm: 4.7k; SizeX_mm: 1; SizeY_mm: 0.5; SizeZ_mm: 0.6; AEC Qualified: N; VDC_V: 50V; AEC Category: Q200
R127 R128 R130 = CMP-0084244-1: RES, 1.0 k, 5%, 0.25 W, AEC-Q200 Grade 0, 0603; Manufacturer: Rohm; Power_W: 250mW; TempCo: 200 ppm/C; SizeAreaWB_mm2: 4.68; Value_Code: 1k00; Value: 1.0k; EIA_Code: E24; Res_ohm: 1k; SizeX_mm: 1.6; SizeY_mm: 0.8; SizeZ_mm: 1; Value2: 0.25W; SizeArea_mm2: 1.28; AEC Qualified: Y; AEC Grade: 0; AEC Category: Q200
R131-R138 R168-R175 R193 = CMP-0025958-3: RES, 10.0 k, 1%, 0.063 W, AEC-Q200 Grade 0, 0402; Manufacturer: Vishay-Dale; Power_W: 63mW; TempCo: 100 ppm/C; Value_Code: 10k0; Value: 10.0k; EIA_Code: E96; Res_ohm: 10k; SizeX_mm: 1; SizeY_mm: 0.5; SizeZ_mm: 0.6; Value2: 0.063W; AEC Qualified: Y; VDC_V: 50V; AEC Category: Q200; AEC Grade: 0
R140 R141 R143 R146 R147 R149 R152 R156 R159 R160 R163 R176-R178 R180-R182 R184 R186 R188-R190 R196 = CMP-0026852-3: RES, 1.0 k, 5%, 0.063 W, AEC-Q200 Grade 0, 0402; Manufacturer: Vishay-Dale; Power_W: 63mW; TempCo: 200 ppm/C; Value_Code: 1k00; Value: 1.0k; EIA_Code: E24; Res_ohm: 1k; SizeX_mm: 1; SizeY_mm: 0.5; SizeZ_mm: 0.6; Value2: 0.063W; AEC Qualified: Y; VDC_V: 50V; AEC Category: Q200; AEC Grade: 0
R144 R150 R155 R157 R162 R164-R167 R179 R183 R187 R191 R233-R236 = CMP-0080661-1: RES, 100 k, 1%, 0.0625 W, AEC-Q200 Grade 0, 0402; Manufacturer: Yageo America; Power_W: 62.5mW; TempCo: 100 ppm/C; SizeAreaWB_mm2: 3; Value: 100k; EIA_Code: E96; SizeX_mm: 1; SizeY_mm: 0.5; SizeZ_mm: 0.6; AEC Qualified: Y; VDC_V: 50V; AEC Grade: 0; AEC Category: Q200
R192 R194 R195 R197-R208 R213 R214 R216 R217 R219 R220 R223 R224 R229-R232 = CMP-0026071-3: RES, 1.00 k, 1%, 0.063 W, AEC-Q200 Grade 0, 0402; Manufacturer: Vishay-Dale; Power_W: 63mW; TempCo: 100 ppm/C; Value_Code: 1k00; Value: 1.00k; EIA_Code: E96; Res_ohm: 1k; SizeX_mm: 1; SizeY_mm: 0.5; SizeZ_mm: 0.6; Value2: 0.063W; AEC Qualified: Y; VDC_V: 50V; AEC Category: Q200; AEC Grade: 0
R210 R212 R225 R228 = CMP-0020617-3: RES, 10, 5%, 0.125 W, AEC-Q200 Grade 0, 0805; Manufacturer: Panasonic; Power_W: 125mW; TempCo: 200 ppm/C; Value_Code: 10R0; Value: 10; EIA_Code: E24; SizeX_mm: 2; SizeY_mm: 1.25; SizeZ_mm: 1.45; Value2: 0.125W; SizeArea_mm2: 2.5; AEC Qualified: Y; VDC_V: 150V; AEC Category: Q200; AEC Grade: 0; SizeAreaWB_mm2: 6.75
R215 R218 R221 R222 = CMP-0017732-3: RES, 80.6, 1%, 0.25 W, AEC-Q200 Grade 0, 1206; Manufacturer: Panasonic; Power_W: 250mW; TempCo: 100 ppm/C; Value_Code: 80R6; Value: 80.6; EIA_Code: E96; SizeX_mm: 3.2; SizeY_mm: 1.6; SizeZ_mm: 1.35; Value2: 0.25W; SizeArea_mm2: 5.12; AEC Qualified: Y; VDC_V: 200V; AEC Category: Q200; AEC Grade: 0; SizeAreaWB_mm2: 10.92
RT1 = CMP-0091865-2: ±1% tolerance 10kΩ linear thermistor available in 0402 and 0603 package options 2-SOT-5X3 -40 to 125; Manufacturer: Texas Instruments; Max Current: 400uA; AEC Qualified: No; TJmax_C: +155°C; TaMin_C: -40°C; TempCo: 6400ppm/°C; TaMax_C: +125°C; VDC_V: 5.5V; SizeZ_mm: 0.77mm; AEC Category: Q200; CompType: IC
U1 = CMP-0065574-3: Automotive 26S/24S Battery Monitor with Smart EIS Engine; Manufacturer: Texas Instruments; SizeZ_mm: 1.2mm; AEC Qualified: Yes; AEC Grade: Grade 1; Number Of Cells: 26; Standoff Height: 0.05mm; AEC Category: Q200; CompType: IC
U2 U3 = CMP-0090991-1: 5-V, 8: 1, 1-channel general-purpose multiplexer with 1.8-V logic control 16-TSSOP -40 to 125; Manufacturer: Texas Instruments; Max Supply Voltage: 5.5V; AEC Qualified: No; PositionCount: 1; Min Supply Voltage: 1.62V; -3Db Bandwith: 350-500MHz; Mux Demux Ratio: 8:1; Nominal Supply Current: 1uA; SizeZ_mm: 1.2mm; TaMin_C: -40°C; TaMax_C: +125°C; Standoff Height: 0.05mm; TJmax_C: +150°C; On State Resistance: 75-650Ω
U4 = CMP-0065077-3: Low-Dropout Regulator, DBV0005A (SOT-23-5); Manufacturer: Texas Instruments; SizeX_mm: 2.8; SizeY_mm: 2.9; CompType: IC; SizeZ_mm: 1.45; SizeArea_mm2: 8.12; SizeAreaWB_mm2: 14.82; AEC Category: Q200; AEC Qualified: N
U5 = CMP-0097640-1: Dual-Supply Inverting Translator with Schmitt-Trigger Input; Manufacturer: Texas Instruments; TJmax_C: +150°C; Number Of Outputs: 1; Data Rate: 420Mbits/s; SizeZ_mm: 1.1mm; V A Max: 5.5V; V B Min: 1.1V; Standoff Height: 0mm; Propagation Delay: 8ns; AEC Qualified: No; Nominal Supply Current: 3uA; TaMax_C: +125°C; TaMin_C: -40°C
Y2 = CMP-0122977-1: 8 MHz ±20ppm Crystal 18pF 150 Ohms 4-SMD, No Lead; Manufacturer: Wurth; Frequency Stability: 30ppm; Frequency_Fixed: 8MHz; SizeZ_mm: 1mm; Esr: 150

## Sheet TIDA-010978_Hardware.SchDoc
size 431 x 279 mm; Date: Not shown in title block; ApprovedBy: Not shown in title block; CheckedBy: Not shown in title block; Author: Not shown in title block; CompanyName: Not shown in title block; Engineer: Not shown in title block; Organization: Not shown in title block; Address1: Not shown in title block; Address2: Not shown in title block; Address3: Not shown in title block; Address4: Not shown in title block; DocumentNumber: 3; Revision: Use project parameter SCH_Rev; SheetNumber: 3; SheetTotal: 3; PageSetup: Record=PageOptions¦CenterHorizontal=True¦CenterVertical=True¦PrintScale=1.00¦XCorrection=1.00¦YCorrection=1.00¦PrintKind=0¦BorderSize=5000000¦LeftOffset=0¦BottomOffset=0¦Orientation=2¦PaperLength=1000¦PaperWidth=1000¦Scale=100¦PaperSource=15¦PrintQuality=600¦MediaType=1¦DitherType=10¦PaperKind=Letter¦PrintScaleMode=1
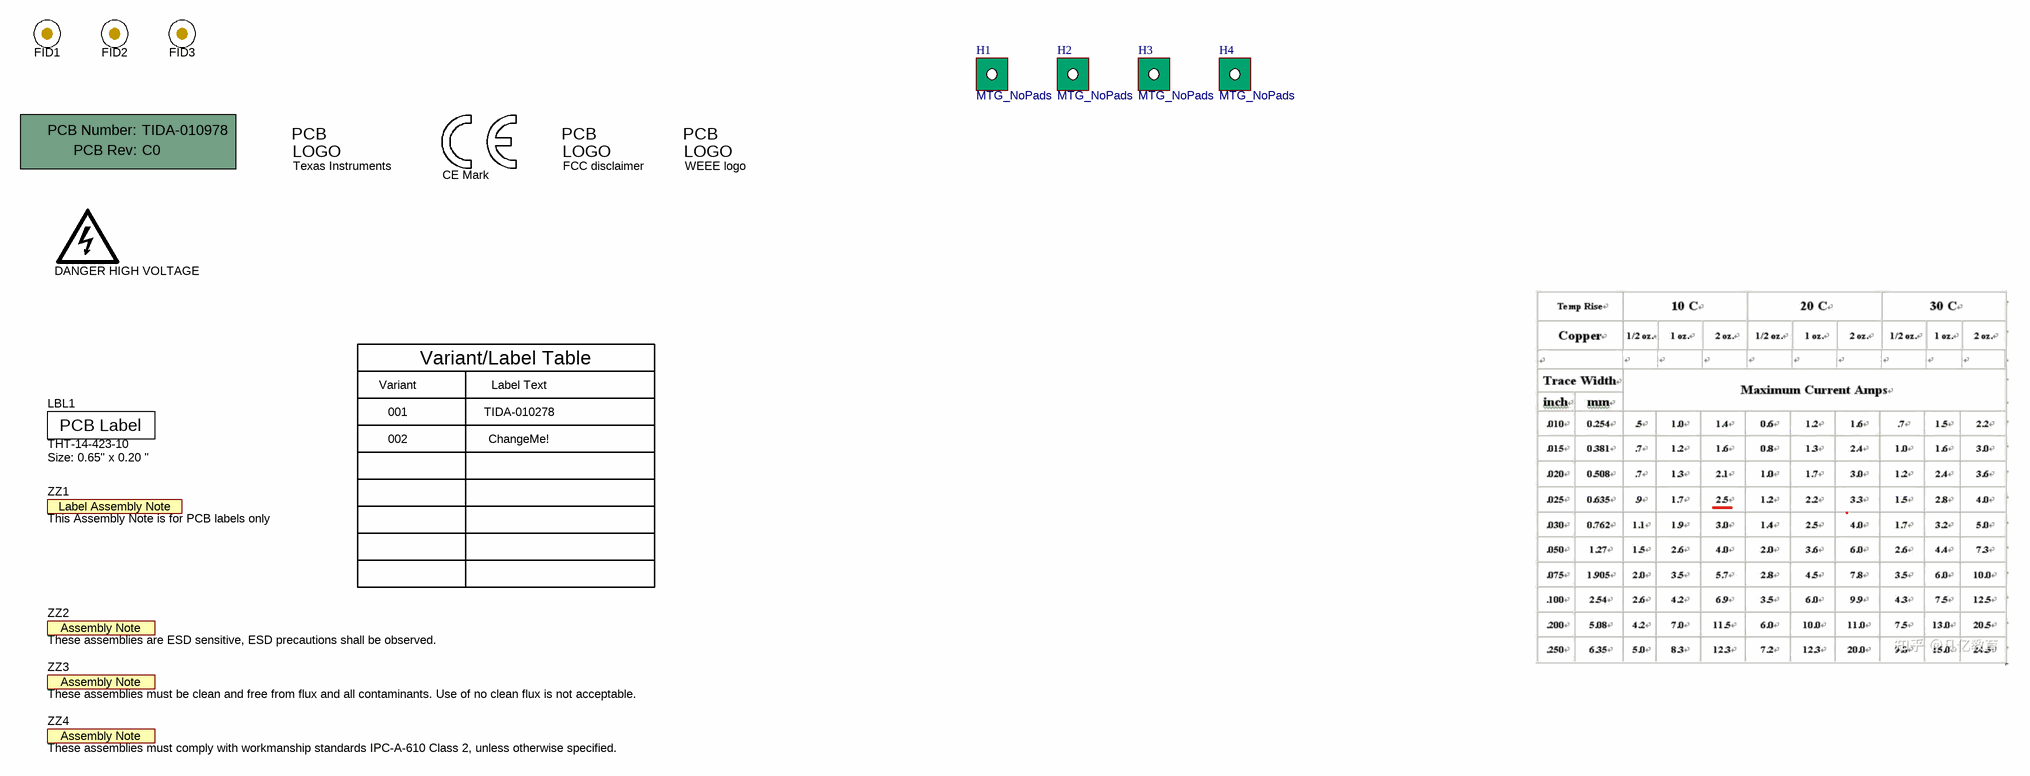
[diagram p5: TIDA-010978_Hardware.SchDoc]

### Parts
!PCB  Printed Circuit Board  (value not drawn)  (mechanical)
FID1  Fiducial  [Fiducial10-20]  (value not drawn)
FID2  Fiducial  [Fiducial10-20]  (value not drawn)
FID3  Fiducial  [Fiducial10-20]  (value not drawn)
H1  MTG_NoPads  [NPTH125mil]  (no BOM)
H2  MTG_NoPads  [NPTH125mil]  (no BOM)
H3  MTG_NoPads  [NPTH125mil]  (no BOM)
H4  MTG_NoPads  [NPTH125mil]  (no BOM)
LBL1  THT-14-423-10  Note: Size: 0.65" x 0.20 "  [Label_650x200]
Logo1  Texas Instruments  [TI_Stacked_Overlay_Small]  (no BOM)
Logo2  CE Mark  [CE_Mark_5mm]  (no BOM)
Logo3  FCC disclaimer  [FCC_disclaimer]  (no BOM)
Logo4  WEEE logo  [WEEE_Minimum]  (no BOM)
LOGO5  DANGER HIGH VOLTAGE  [IEC_HighVoltage_Small]  (no BOM)
ZZ1  This Assembly Note is for PCB labels only  [AssemblyNoteLabel]  (no BOM)
ZZ2  These assemblies are ESD sensitive, ESD precautions shall be observed.  [AssemblyNote]  (no BOM)
ZZ3  These assemblies must be clean and free from flux and all contaminants. Use of no clean flux is not acceptable.  [AssemblyNote]  (no BOM)
ZZ4  These assemblies must comply with workmanship standards IPC-A-610 Class 2, unless otherwise specified.  [AssemblyNote]  (no BOM)

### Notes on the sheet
- Variant
- Variant/Label Table
- Label Text
- 001
- 002
- TIDA-010278
- ChangeMe!

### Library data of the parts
!PCB = CMP-0003618-2: Manufacturer: Any; PartNumber: TIDA-010978
FID1-FID3 = CMP-0077181-1: Fiducial mark.  There is nothing to buy or mount.
H1-H4 = CMP-0078424-2: PCB Mounting Hole, No Pad; Manufacturer: Any; Key: Mounting Hole (non-standard) No Pad
LBL1 = CMP-0003625-1: Thermal Transfer Printable Labels, 0.650" W x 0.200" H - 10,000 per roll; Manufacturer: Brady; CompType: Label
Logo1 = CMP-0074838-1: Texas Instrument Corporate Signature; SymbolCreator: a0412235; Lib Reference: TI_Logo; Library Reference: Logo
Logo2 = CMP-0074844-1: SymbolCreator: a0412235
Logo3 = CMP-0074847-1: FCC_disclaimer; Library Reference: Logo
Logo4 = CMP-0074769-1
LOGO5 = CMP-0074835-1: IEC 61010-1 High Voltage Warning; SymbolCreator: a0412235; Lib Reference: IEC_HighVoltage
ZZ1 = CMP-0003616-3
ZZ2 = CMP-0077236-1
ZZ3 = CMP-0077237-1
ZZ4 = CMP-0077238-1

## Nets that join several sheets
GND: TIDA-010978 (5 pins), A1 (156 pins), A2 (156 pins)
COMMH_N_OPT: TIDA-010978 (C6.1 T2.3), A1 (C154_A1.2 R222_A1.1 R228_A1.2)
COMMH_N_OPT: TIDA-010978 (T3.6), A2 (C154_A2.2 R222_A2.1 R228_A2.2)
COMMH_P_OPT: TIDA-010978 (C1.1 T2.1), A1 (C147_A1.1 R212_A1.2 R218_A1.2)
COMMH_P_OPT: TIDA-010978 (T3.4), A2 (C147_A2.1 R212_A2.2 R218_A2.2)
COMML_N_OPT: TIDA-010978 (C7.2 T2.4), A2 (C149_A2.2 R221_A2.1 R225_A2.1)
COMML_N_OPT: TIDA-010978 (T1.4), A1 (C149_A1.2 R221_A1.1 R225_A1.1)
COMML_P_OPT: TIDA-010978 (C2.2 T2.6), A2 (C148_A2.1 R210_A2.1 R215_A2.2)
COMML_P_OPT: TIDA-010978 (T1.6), A1 (C148_A1.1 R210_A1.1 R215_A1.2)

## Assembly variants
001: not fitted C1 C2 C6 C7 C18_A1 C18_A2 C20_A1 C20_A2 C32_A1 C32_A2 C33_A2 C38_A2 C38_A2 C38_A2 C39_A1 C39_A2 C40_A2 C51_A2 C51_A2 C52_A1 C52_A2 C52_A2 C122_A1 C122_A2 C124_A1 C124_A1 C124_A1 C124_A2 C124_A2 C124_A2 C128_A1 C128_A1 C128_A1 C128_A2 C128_A2 C128_A2 C155_A2 C158_A2 C159_A2 C160_A2 C161_A2 C?_A1 C?_A1 C?_A1 FID2 FID3 J7_A2 J11_A2 J12_A1 J12_A2 R20_A1 R20_A2 R55_A2 R56_A2 R57_A2 R70_A2 R76_A2 R76_A2 R76_A2 R79_A2 R155_A2 R162_A2 R165_A2 R166_A2 R167_A2 R233_A1 R233_A2 R234_A1 R234_A2 R235_A1 R235_A2 R236_A1 R236_A2 U2_A1 U3_A1 U4_A2 U5_A2 Y1_A1 Y1_A2 Y2_A1 Y2_A2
